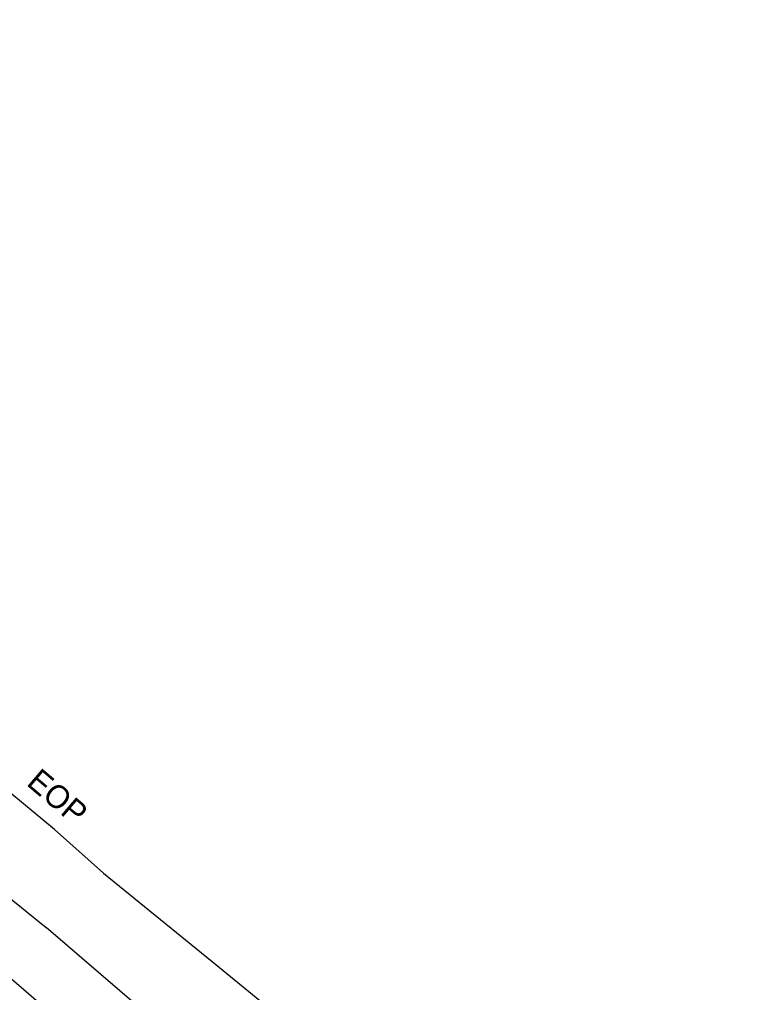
# Model space of a CAD drawing. Extents: x 2076109 to 2080761, y 592812 to 596750.
# Drawn here: x 2076824.7 to 2076981.7, y 596326.7 to 596538.4 of the extents above; entities that cross this region are included whole.
import ezdxf

# ---------------------------------------------------------------- set-up
doc = ezdxf.new("R2010")
doc.units = 0
for name, color, linetype in [('RD_EX_Fence_ChLk', 7, 'Continuous'), ('RD_EX_Road', 7, 'Continuous'), ('RD_EX_Road_txCode', 7, 'Continuous')]:
    doc.layers.add(name, color=color, linetype=linetype)

msp = doc.modelspace()

# ---------------------------------------------------------------- linework, layer by layer
at = {"layer": 'RD_EX_Fence_ChLk'}
msp.add_lwpolyline([(2076822.97, 596329.73), (2076907.02, 596257.07), (2076948.27, 596221.63), (2077023.38, 596156.57), (2077092.73, 596094.04)], dxfattribs=at)
msp.add_lwpolyline([(2076822.97, 596329.73), (2076907.02, 596257.07), (2076948.27, 596221.63), (2077023.38, 596156.57), (2077092.73, 596094.04)], dxfattribs=at)
at = {"layer": 'RD_EX_Road'}
for points in [[(2076842.97, 596352.71), (2076832.37, 596362.19), (2076820.52, 596372), (2076794.64, 596393.55), (2076774.42, 596413.16), (2076753.99, 596431.61), (2076731.69, 596450.01), (2076701.65, 596478.13), (2076672.55, 596503.52), (2076646.56, 596525.28), (2076627.87, 596540.71), (2076592.82, 596570.89), (2076568.98, 596591.67), (2076548.54, 596609.33), (2076527.99, 596626.43), (2076515.1, 596637.29), (2076494.85, 596655.12), (2076477.27, 596670.31), (2076468.82, 596677.3), (2076461.99, 596669.18), (2076455.15, 596661.07)], [(2076842.97, 596352.71), (2076832.37, 596362.19), (2076820.52, 596372), (2076794.64, 596393.55), (2076774.42, 596413.16), (2076753.99, 596431.61), (2076731.69, 596450.01), (2076701.65, 596478.13), (2076672.55, 596503.52), (2076646.56, 596525.28), (2076627.87, 596540.71), (2076592.82, 596570.89), (2076568.98, 596591.67), (2076548.54, 596609.33), (2076527.99, 596626.43), (2076515.1, 596637.29), (2076494.85, 596655.12), (2076477.27, 596670.31), (2076468.82, 596677.3), (2076461.99, 596669.18), (2076455.15, 596661.07)], [(2076455.15, 596661.07), (2076476.63, 596642.92), (2076494.95, 596628.34), (2076515.98, 596609.91), (2076530.88, 596597.77), (2076547.6, 596583.48), (2076561.23, 596571.31), (2076579.89, 596554.59), (2076592.31, 596544.26), (2076607.07, 596531.52), (2076649.41, 596493.37), (2076665.89, 596479.72), (2076693.1, 596458.59), (2076737.13, 596423.64), (2076779.57, 596383.19), (2076807.07, 596359.79), (2076830.55, 596340.86)], [(2076455.15, 596661.07), (2076476.63, 596642.92), (2076494.95, 596628.34), (2076515.98, 596609.91), (2076530.88, 596597.77), (2076547.6, 596583.48), (2076561.23, 596571.31), (2076579.89, 596554.59), (2076592.31, 596544.26), (2076607.07, 596531.52), (2076649.41, 596493.37), (2076665.89, 596479.72), (2076693.1, 596458.59), (2076737.13, 596423.64), (2076779.57, 596383.19), (2076807.07, 596359.79), (2076830.55, 596340.86)], [(2076842.97, 596352.71), (2076866.66, 596333.49), (2076894.56, 596310.65), (2076921.28, 596287.84), (2076946.98, 596265.34), (2076974.88, 596240.88), (2077000.65, 596218.69), (2077026.03, 596196.79), (2077056.62, 596170.55), (2077088.59, 596142.9), (2077102.76, 596132.06), (2077111.62, 596125.08), (2077125.62, 596114.47), (2077137.22, 596107.56), (2077155.37, 596096.64), (2077165.33, 596091.21), (2077183.91, 596082.52), (2077199.74, 596075.75), (2077216.78, 596070.63), (2077234.93, 596066.86), (2077254.14, 596063.85), (2077265.17, 596063.1), (2077275.23, 596063.54), (2077294.18, 596061.91)], [(2076842.97, 596352.71), (2076866.66, 596333.49), (2076894.56, 596310.65), (2076921.28, 596287.84), (2076946.98, 596265.34), (2076974.88, 596240.88), (2077000.65, 596218.69), (2077026.03, 596196.79), (2077056.62, 596170.55), (2077088.59, 596142.9), (2077102.76, 596132.06), (2077111.62, 596125.08), (2077125.62, 596114.47), (2077137.22, 596107.56), (2077155.37, 596096.64), (2077165.33, 596091.21), (2077183.91, 596082.52), (2077199.74, 596075.75), (2077216.78, 596070.63), (2077234.93, 596066.86), (2077254.14, 596063.85), (2077265.17, 596063.1), (2077275.23, 596063.54), (2077294.18, 596061.91)], [(2077310.8, 596045.6), (2077284.61, 596043.93), (2077263.73, 596044.86), (2077236.77, 596048.36), (2077217.91, 596052.27), (2077187.35, 596060.96), (2077164.2, 596069.76), (2077147.2, 596077.8), (2077123.41, 596090.88), (2077107.36, 596101.02), (2077085.71, 596117.86), (2077071.4, 596130.86), (2077033.15, 596164.21), (2077005.12, 596187.54), (2076967.19, 596220.06), (2076925.04, 596258.57), (2076895.71, 596284.71), (2076870.35, 596306.64), (2076830.55, 596340.86)], [(2077310.8, 596045.6), (2077284.61, 596043.93), (2077263.73, 596044.86), (2077236.77, 596048.36), (2077217.91, 596052.27), (2077187.35, 596060.96), (2077164.2, 596069.76), (2077147.2, 596077.8), (2077123.41, 596090.88), (2077107.36, 596101.02), (2077085.71, 596117.86), (2077071.4, 596130.86), (2077033.15, 596164.21), (2077005.12, 596187.54), (2076967.19, 596220.06), (2076925.04, 596258.57), (2076895.71, 596284.71), (2076870.35, 596306.64), (2076830.55, 596340.86)]]:
    msp.add_lwpolyline(points, dxfattribs=at)

# ---------------------------------------------------------------- texts
at = {"layer": 'RD_EX_Road_txCode'}
msp.add_text('EOP', height=5, rotation=319.6274, dxfattribs=at).set_placement((2076826.02, 596371.99))
msp.add_text('EOP', height=5, rotation=319.6274, dxfattribs=at).set_placement((2076826.02, 596371.99))

doc.saveas('drawing.dxf')
